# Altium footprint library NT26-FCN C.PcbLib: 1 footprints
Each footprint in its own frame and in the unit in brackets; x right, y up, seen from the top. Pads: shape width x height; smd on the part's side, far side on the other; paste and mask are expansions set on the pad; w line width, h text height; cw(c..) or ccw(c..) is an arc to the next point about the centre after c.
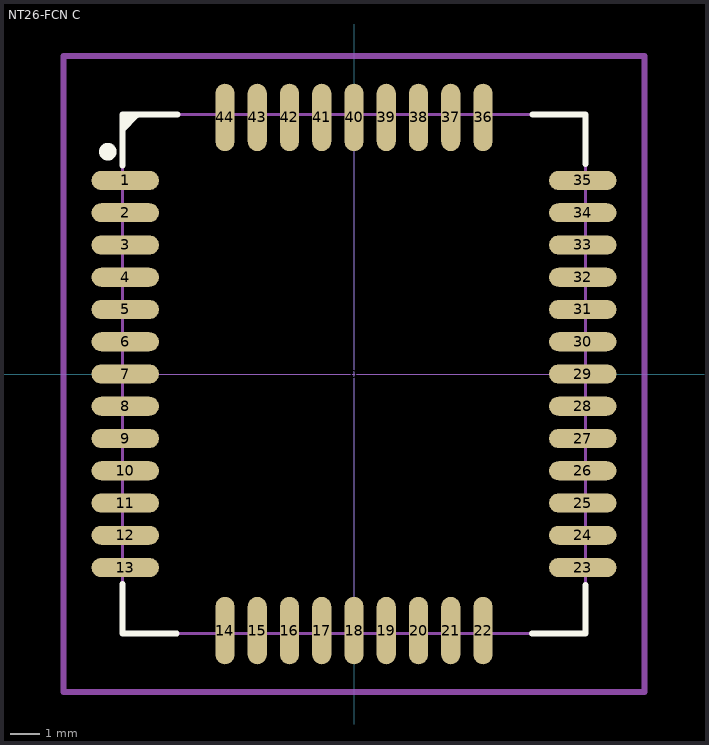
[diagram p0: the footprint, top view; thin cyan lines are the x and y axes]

## NT26-FCN C [mm]
pads (46):
  round 0.8 on Mech1 mask+0.051: 0(-6.457,7.619)
  round 0.5 on Mech1: 0(0,0)
  oval 2.3x0.65 smd: 1(-7.8,6.6) 2(-7.8,5.5) 3(-7.8,4.4) 4(-7.8,3.3) 5(-7.8,2.2) 6(-7.8,1.1) 7(-7.8,0) 8(-7.8,-1.1) 9(-7.8,-2.2) 10(-7.8,-3.3) 11(-7.8,-4.4) 12(-7.8,-5.5) 13(-7.8,-6.6) 23(7.8,-6.6) 24(7.8,-5.5) 25(7.8,-4.4) 26(7.8,-3.3) 27(7.8,-2.2) 28(7.8,-1.1) 29(7.8,0) 30(7.8,1.1) 31(7.8,2.2) 32(7.8,3.3) 33(7.8,4.4) 34(7.8,5.5) 35(7.8,6.6)
  oval 0.65x2.3 smd: 14(-4.4,-8.75) 15(-3.3,-8.75) 16(-2.2,-8.75) 17(-1.1,-8.75) 18(0,-8.75) 19(1.1,-8.75) 20(2.2,-8.75) 21(3.3,-8.75) 22(4.4,-8.75) 36(4.4,8.75) 37(3.3,8.75) 38(2.2,8.75) 39(1.1,8.75) 40(0,8.75) 41(-1.1,8.75) 42(-2.2,8.75) 43(-3.3,8.75) 44(-4.4,8.75)
Top Overlay:
  circle w0.4: c-8.395,7.58 r0.1
  lines w0.2: -7.9,-7.163 -7.9,-8.85 -6.046,-8.85 ; -7.9,7.112 -7.9,8.85 -6.019,8.85 ; -7.595,8.814 -7.899,8.509 -7.899,8.331 -7.417,8.814 ; 6.07,-8.85 7.9,-8.85 7.9,-7.192 ; 6.085,8.85 7.9,8.85 7.9,7.159
Mechanical 1:
  lines w0.01: -7.9,0 7.9,0 ; 0,-8.85 0,8.85
  lines w0.1: -7.9,8.85 -7.9,-8.85 7.9,-8.85 7.9,8.85 ; -7.9,8.85 7.9,8.85 ; -7.9,8.85 7.9,8.85 ; -7.9,8.85 -7.9,-8.85 7.9,-8.85 7.9,8.85
  lines w0.2: -9.9,-10.85 9.9,-10.85 9.9,10.85 -9.9,10.85 -9.9,-10.85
